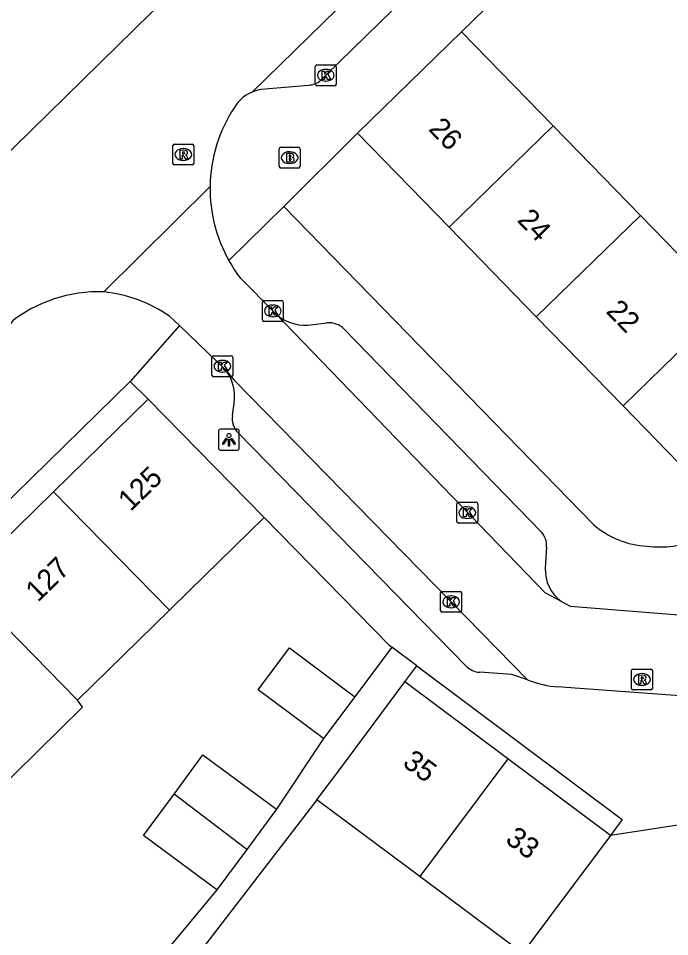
# Model space of a CAD drawing. Extents: x 159222 to 160346, y 381249 to 382166.
# Drawn here: x 159523.05 to 159554.22, y 381384.14 to 381428.08 of the extents above; entities that cross this region are included whole.
import ezdxf

# ---------------------------------------------------------------- set-up
doc = ezdxf.new("R2010")
doc.units = 0
for name, color, linetype in [('IMGEO_Brandkraan', 7, 'Continuous'), ('IMGEO_Kolk', 7, 'Continuous'), ('IMGEO_Lichtpunt', 7, 'Continuous'), ('IMGEO_Muur', 7, 'Continuous'), ('IMGEO_Pand', 7, 'Continuous'), ('IMGEO_Pand_nummerreeks', 7, 'Continuous'), ('IMGEO_Rijbaan_lokaal_gesloten', 7, 'Continuous'), ('IMGEO_Rijbaan_lokaal_open', 7, 'Continuous'), ('IMGEO_Rioolput', 7, 'Continuous'), ('IMGEO_Voetpad_open', 7, 'Continuous')]:
    doc.layers.add(name, color=color, linetype=linetype)

msp = doc.modelspace()

# ---------------------------------------------------------------- linework, layer by layer
at = {"layer": 'IMGEO_Brandkraan'}
for p, q in [((159535.53, 381420.985), (159535.53, 381421.837)), ((159535.605, 381421.911), (159536.457, 381421.911)), ((159536.018, 381421.691), (159536.043, 381421.691)), ((159536.531, 381421.837), (159536.531, 381420.985)), ((159536.041, 381421.131), (159536.016, 381421.131)), ((159536.457, 381420.911), (159535.605, 381420.911))]:
    msp.add_line(p, q, dxfattribs=at)
for points in [[(159535.53, 381420.985), (159535.53, 381421.837)], [(159535.605, 381421.911), (159536.457, 381421.911)], [(159535.878, 381421.611), (159535.878, 381421.211), (159536.091, 381421.211)], [(159536.109, 381421.611), (159535.878, 381421.611)], [(159536.057, 381421.53), (159536.003, 381421.53), (159536.003, 381421.454)], [(159536.531, 381421.837), (159536.531, 381420.985)], [(159536.003, 381421.454), (159536.056, 381421.454)], [(159536.065, 381421.378), (159536.003, 381421.378), (159536.003, 381421.297)], [(159536.003, 381421.297), (159536.065, 381421.297)], [(159536.457, 381420.911), (159535.605, 381420.911)]]:
    msp.add_lwpolyline(points, dxfattribs=at)
for centre, radius, start, end in [((159535.607, 381421.835), 0.0765, 91.552, 178.448), ((159535.607, 381421.835), 0.0765, 91.552, 178.448), ((159536.058, 381421.492), 0.0379, 267.8285, 90.9355), ((159536.113, 381421.466), 0.145, 59.4692, 91.5367), ((159536.138, 381421.513), 0.0922, 285.5137, 58.1501), ((159536.455, 381421.835), 0.0765, 1.552, 88.448), ((159536.455, 381421.835), 0.0765, 1.552, 88.448), ((159536.066, 381421.337), 0.0404, 269.8759, 90.5077), ((159536.097, 381421.462), 0.251, 268.6676, 293.5347), ((159536.143, 381421.321), 0.105, 301.3115, 78.989), ((159535.607, 381420.987), 0.0765, 181.552, 268.448), ((159535.607, 381420.987), 0.0765, 181.552, 268.448), ((159536.455, 381420.987), 0.0765, 271.552, 358.448), ((159536.455, 381420.987), 0.0765, 271.552, 358.448)]:
    msp.add_arc(centre, radius, start, end, dxfattribs=at)
for centre, major_axis, ratio, start_param, end_param in [((159536.017, 381421.411), (-0.387, 0.002), 0.722429, 4.712389, 7.853982), ((159536.042, 381421.411), (-0.39, 0.002), 0.717154, 1.570796, 4.712389)]:
    msp.add_ellipse(centre, major_axis=major_axis, ratio=ratio, start_param=start_param, end_param=end_param, dxfattribs=at)
at = {"layer": 'IMGEO_Kolk'}
for p, q in [((159537.259, 381424.928), (159537.259, 381425.78)), ((159537.334, 381425.854), (159538.186, 381425.854)), ((159537.747, 381425.634), (159537.772, 381425.634)), ((159538.26, 381425.78), (159538.26, 381424.928)), ((159537.77, 381425.074), (159537.745, 381425.074)), ((159538.186, 381424.854), (159537.334, 381424.854)), ((159534.725, 381413.649), (159534.725, 381414.501)), ((159534.8, 381414.575), (159535.652, 381414.575)), ((159535.726, 381414.501), (159535.726, 381413.649)), ((159535.213, 381414.355), (159535.238, 381414.355)), ((159535.236, 381413.795), (159535.211, 381413.795)), ((159535.652, 381413.575), (159534.8, 381413.575)), ((159532.31, 381411.003), (159532.31, 381411.855)), ((159532.385, 381411.929), (159533.237, 381411.929)), ((159533.311, 381411.855), (159533.311, 381411.003)), ((159532.798, 381411.709), (159532.823, 381411.709)), ((159532.821, 381411.149), (159532.796, 381411.149)), ((159533.237, 381410.929), (159532.385, 381410.929)), ((159544.031, 381403.998), (159544.031, 381404.85)), ((159544.106, 381404.924), (159544.958, 381404.924)), ((159545.032, 381404.85), (159545.032, 381403.998)), ((159544.519, 381404.704), (159544.544, 381404.704)), ((159544.542, 381404.144), (159544.517, 381404.144)), ((159544.958, 381403.924), (159544.106, 381403.924)), ((159543.256, 381399.73), (159543.256, 381400.582)), ((159543.331, 381400.656), (159544.183, 381400.656)), ((159543.744, 381400.436), (159543.769, 381400.436)), ((159544.257, 381400.582), (159544.257, 381399.73)), ((159544.183, 381399.656), (159543.331, 381399.656)), ((159543.767, 381399.876), (159543.742, 381399.876))]:
    msp.add_line(p, q, dxfattribs=at)
for points in [[(159537.259, 381424.928), (159537.259, 381425.78)], [(159537.334, 381425.854), (159538.186, 381425.854)], [(159537.58, 381425.554), (159537.703, 381425.554), (159537.703, 381425.403), (159537.833, 381425.554), (159537.997, 381425.554), (159537.851, 381425.403), (159538.004, 381425.154), (159537.852, 381425.154), (159537.767, 381425.318), (159537.703, 381425.251), (159537.703, 381425.154), (159537.58, 381425.154), (159537.58, 381425.554)], [(159538.26, 381425.78), (159538.26, 381424.928)], [(159538.186, 381424.854), (159537.334, 381424.854)], [(159534.725, 381413.649), (159534.725, 381414.501)], [(159534.8, 381414.575), (159535.652, 381414.575)], [(159535.726, 381414.501), (159535.726, 381413.649)], [(159535.046, 381414.275), (159535.169, 381414.275), (159535.169, 381414.124), (159535.299, 381414.275), (159535.463, 381414.275), (159535.317, 381414.124), (159535.47, 381413.875), (159535.318, 381413.875), (159535.233, 381414.039), (159535.169, 381413.972), (159535.169, 381413.875), (159535.046, 381413.875), (159535.046, 381414.275)], [(159535.652, 381413.575), (159534.8, 381413.575)], [(159532.31, 381411.003), (159532.31, 381411.855)], [(159532.385, 381411.929), (159533.237, 381411.929)], [(159533.311, 381411.855), (159533.311, 381411.003)], [(159532.631, 381411.629), (159532.754, 381411.629), (159532.754, 381411.478), (159532.884, 381411.629), (159533.048, 381411.629), (159532.902, 381411.478), (159533.055, 381411.229), (159532.903, 381411.229), (159532.818, 381411.393), (159532.754, 381411.326), (159532.754, 381411.229), (159532.631, 381411.229), (159532.631, 381411.629)], [(159533.237, 381410.929), (159532.385, 381410.929)], [(159544.031, 381403.998), (159544.031, 381404.85)], [(159544.106, 381404.924), (159544.958, 381404.924)], [(159545.032, 381404.85), (159545.032, 381403.998)], [(159544.352, 381404.624), (159544.475, 381404.624), (159544.475, 381404.473), (159544.605, 381404.624), (159544.769, 381404.624), (159544.623, 381404.473), (159544.776, 381404.224), (159544.624, 381404.224), (159544.539, 381404.388), (159544.475, 381404.321), (159544.475, 381404.224), (159544.352, 381404.224), (159544.352, 381404.624)], [(159544.958, 381403.924), (159544.106, 381403.924)], [(159543.256, 381399.73), (159543.256, 381400.582)], [(159543.331, 381400.656), (159544.183, 381400.656)], [(159544.257, 381400.582), (159544.257, 381399.73)], [(159543.577, 381400.356), (159543.7, 381400.356), (159543.7, 381400.205), (159543.83, 381400.356), (159543.994, 381400.356), (159543.848, 381400.205), (159544.001, 381399.956), (159543.849, 381399.956), (159543.764, 381400.12), (159543.7, 381400.053), (159543.7, 381399.956), (159543.577, 381399.956), (159543.577, 381400.356)], [(159544.183, 381399.656), (159543.331, 381399.656)]]:
    msp.add_lwpolyline(points, dxfattribs=at)
for centre, start, end in [((159537.336, 381425.778), 91.552, 178.448), ((159537.336, 381425.778), 91.552, 178.448), ((159538.184, 381425.778), 1.552, 88.448), ((159538.184, 381425.778), 1.552, 88.448), ((159537.336, 381424.93), 181.552, 268.448), ((159537.336, 381424.93), 181.552, 268.448), ((159538.184, 381424.93), 271.552, 358.448), ((159538.184, 381424.93), 271.552, 358.448), ((159534.802, 381414.499), 91.552, 178.448), ((159534.802, 381414.499), 91.552, 178.448), ((159535.65, 381414.499), 1.552, 88.448), ((159535.65, 381414.499), 1.552, 88.448), ((159534.802, 381413.651), 181.552, 268.448), ((159534.802, 381413.651), 181.552, 268.448), ((159535.65, 381413.651), 271.552, 358.448), ((159535.65, 381413.651), 271.552, 358.448), ((159532.387, 381411.853), 91.552, 178.448), ((159532.387, 381411.853), 91.552, 178.448), ((159533.235, 381411.853), 1.552, 88.448), ((159533.235, 381411.853), 1.552, 88.448), ((159532.387, 381411.005), 181.552, 268.448), ((159532.387, 381411.005), 181.552, 268.448), ((159533.235, 381411.005), 271.552, 358.448), ((159533.235, 381411.005), 271.552, 358.448), ((159544.108, 381404.848), 91.552, 178.448), ((159544.108, 381404.848), 91.552, 178.448), ((159544.956, 381404.848), 1.552, 88.448), ((159544.956, 381404.848), 1.552, 88.448), ((159544.108, 381404), 181.552, 268.448), ((159544.108, 381404), 181.552, 268.448), ((159544.956, 381404), 271.552, 358.448), ((159544.956, 381404), 271.552, 358.448), ((159543.333, 381400.58), 91.552, 178.448), ((159543.333, 381400.58), 91.552, 178.448), ((159544.181, 381400.58), 1.552, 88.448), ((159544.181, 381400.58), 1.552, 88.448), ((159543.333, 381399.732), 181.552, 268.448), ((159543.333, 381399.732), 181.552, 268.448), ((159544.181, 381399.732), 271.552, 358.448), ((159544.181, 381399.732), 271.552, 358.448)]:
    msp.add_arc(centre, 0.0765, start, end, dxfattribs=at)
for centre, major_axis, ratio, start_param, end_param in [((159537.746, 381425.354), (-0.387, 0.002), 0.722429, 4.712389, 7.853982), ((159537.771, 381425.354), (-0.39, 0.002), 0.717154, 1.570796, 4.712389), ((159535.212, 381414.075), (-0.387, 0.002), 0.722429, 4.712389, 7.853982), ((159535.237, 381414.075), (-0.39, 0.002), 0.717154, 1.570796, 4.712389), ((159532.797, 381411.429), (-0.387, 0.002), 0.722429, 4.712389, 7.853982), ((159532.822, 381411.429), (-0.39, 0.002), 0.717154, 1.570796, 4.712389), ((159544.518, 381404.424), (-0.387, 0.002), 0.722429, 4.712389, 7.853982), ((159544.543, 381404.424), (-0.39, 0.002), 0.717154, 1.570796, 4.712389), ((159543.743, 381400.156), (-0.387, 0.002), 0.722429, 4.712389, 7.853982), ((159543.768, 381400.156), (-0.39, 0.002), 0.717154, 1.570796, 4.712389)]:
    msp.add_ellipse(centre, major_axis=major_axis, ratio=ratio, start_param=start_param, end_param=end_param, dxfattribs=at)
at = {"layer": 'IMGEO_Lichtpunt'}
for p, q in [((159533.527, 381408.412), (159532.719, 381408.412)), ((159533.527, 381408.412), (159532.719, 381408.412)), ((159532.625, 381408.317), (159532.625, 381407.51)), ((159532.625, 381408.317), (159532.625, 381407.51)), ((159533.621, 381407.51), (159533.621, 381408.317)), ((159533.621, 381407.51), (159533.621, 381408.317)), ((159532.719, 381407.416), (159533.527, 381407.416)), ((159532.719, 381407.416), (159533.527, 381407.416))]:
    msp.add_line(p, q, dxfattribs=at)
for points in [[(159532.999, 381407.981), (159533.038, 381407.953), (159532.85, 381407.691), (159532.812, 381407.718), (159532.999, 381407.981)], [(159533.101, 381407.933), (159533.148, 381407.933), (159533.148, 381407.611), (159533.101, 381407.611), (159533.101, 381407.933)], [(159533.211, 381407.953), (159533.249, 381407.98), (159533.436, 381407.718), (159533.397, 381407.69), (159533.211, 381407.953)]]:
    msp.add_lwpolyline(points, dxfattribs=at)
msp.add_circle((159533.124, 381408.115), 0.0994, dxfattribs=at)
for centre, start, end in [((159532.719, 381408.317), 90, 180), ((159532.719, 381408.317), 90, 180), ((159533.527, 381408.317), 0, 90), ((159533.527, 381408.317), 0, 90), ((159532.719, 381407.51), 180, 270), ((159532.719, 381407.51), 180, 270), ((159533.527, 381407.51), 270, 0), ((159533.527, 381407.51), 270, 360)]:
    msp.add_arc(centre, 0.0946, start, end, dxfattribs=at)
at = {"layer": 'IMGEO_Muur'}
msp.add_lwpolyline([(159540.781, 381398.099), (159534.803, 381404.193)], dxfattribs=at)
at = {"layer": 'IMGEO_Pand'}
for points in [[(159539.277, 381422.576), (159544.261, 381427.431)], [(159544.261, 381427.431), (159548.642, 381422.933)], [(159548.642, 381422.933), (159543.659, 381418.078)], [(159548.642, 381422.933), (159552.816, 381418.649)], [(159543.659, 381418.078), (159539.277, 381422.576)], [(159547.832, 381413.793), (159552.816, 381418.649)], [(159552.816, 381418.649), (159556.971, 381414.383)], [(159547.832, 381413.793), (159543.659, 381418.078)], [(159556.971, 381414.383), (159561.255, 381409.985), (159567.026, 381412.071), (159568.52, 381407.973), (159561.062, 381405.254), (159558.383, 381407.188), (159556.271, 381405.13), (159551.987, 381409.527)], [(159556.971, 381414.383), (159551.987, 381409.527)], [(159551.987, 381409.527), (159547.832, 381413.793)], [(159529.252, 381409.859), (159524.724, 381405.421)], [(159529.252, 381409.859), (159534.803, 381404.193)], [(159524.724, 381405.421), (159520.331, 381401.117)], [(159524.724, 381405.421), (159530.275, 381399.757)], [(159530.275, 381399.757), (159531.232, 381400.694), (159534.803, 381404.193)], [(159525.882, 381395.453), (159520.331, 381401.117)], [(159525.882, 381395.453), (159530.275, 381399.757)], [(159537.652, 381393.612), (159534.527, 381395.944), (159536.022, 381397.948), (159539.147, 381395.616)], [(159537.336, 381390.68), (159538.555, 381392.313), (159541.545, 381396.32)], [(159546.464, 381392.649), (159541.545, 381396.32)], [(159539.147, 381395.616), (159537.652, 381393.612)], [(159521.776, 381390.857), (159526.123, 381395.12), (159525.882, 381395.453)], [(159530.5, 381390.959), (159531.881, 381392.828), (159535.399, 381390.23)], [(159546.464, 381392.649), (159542.257, 381387.008)], [(159551.383, 381388.978), (159546.464, 381392.649)], [(159532.55, 381386.372), (159529.032, 381388.97), (159530.5, 381390.959)], [(159533.978, 381388.307), (159530.5, 381390.959)], [(159542.257, 381387.008), (159537.336, 381390.68)], [(159535.399, 381390.23), (159533.978, 381388.307)], [(159551.383, 381388.978), (159548.394, 381384.971), (159547.175, 381383.338), (159542.257, 381387.008)], [(159533.978, 381388.307), (159532.55, 381386.372)]]:
    msp.add_lwpolyline(points, dxfattribs=at)
at = {"layer": 'IMGEO_Rijbaan_lokaal_gesloten'}
for points in [[(159534.231, 381424.544), (159557.976, 381447.733)], [(159533.511, 381432.388), (159520.372, 381419.512)], [(159534.231, 381424.544), (159534.207, 381424.535), (159534.062, 381424.464), (159533.924, 381424.381), (159533.795, 381424.285), (159533.674, 381424.179), (159533.563, 381424.062), (159533.464, 381423.935), (159533.384, 381423.815)], [(159532.224, 381420.031), (159527.135, 381414.989)], [(159527.135, 381414.989), (159526.531, 381414.985), (159525.93, 381414.928), (159525.336, 381414.817), (159524.755, 381414.653), (159524.19, 381414.439), (159523.647, 381414.174), (159523.13, 381413.862), (159522.909, 381413.709), (159522.787, 381413.6), (159522.676, 381413.48), (159522.6, 381413.383)]]:
    msp.add_lwpolyline(points, dxfattribs=at)
msp.add_arc((159539.296, 381419.933), 7.073, 146.7098, 179.204, dxfattribs=at)
at = {"layer": 'IMGEO_Rijbaan_lokaal_open'}
for points in [[(159533.656, 381415.663), (159535.334, 381413.963)], [(159530.28, 381413.823), (159530.752, 381413.378)], [(159549.041, 381400.165), (159548.266, 381400.58), (159535.334, 381413.963)], [(159532.945, 381411.28), (159530.752, 381413.378)], [(159532.945, 381411.28), (159533.378, 381410.764), (159547.413, 381396.42)], [(159549.041, 381400.165), (159549.457, 381399.942), (159555.859, 381399.431), (159556.544, 381399.493)], [(159557.302, 381395.935), (159556.228, 381395.543), (159549.264, 381396.063), (159548.892, 381396.081)]]:
    msp.add_lwpolyline(points, dxfattribs=at)
for centre, radius, start, end in [((159539.288, 381419.928), 7.065, 179.1685, 209.1323), ((159539.348, 381419.966), 7.136, 209.1632, 217.0891), ((159526.488, 381408.419), 6.601, 54.9406, 84.3751), ((159549.338, 381401.422), 5.36, 248.9529, 265.2276)]:
    msp.add_arc(centre, radius, start, end, dxfattribs=at)
at = {"layer": 'IMGEO_Rioolput'}
for p, q in [((159530.441, 381421.136), (159530.441, 381421.988)), ((159530.516, 381422.062), (159531.368, 381422.062)), ((159531.442, 381421.988), (159531.442, 381421.136)), ((159530.929, 381421.842), (159530.954, 381421.842)), ((159530.952, 381421.282), (159530.927, 381421.282)), ((159531.368, 381421.062), (159530.516, 381421.062)), ((159552.466, 381396.939), (159553.318, 381396.939)), ((159552.391, 381396.013), (159552.391, 381396.865)), ((159552.879, 381396.719), (159552.904, 381396.719)), ((159553.392, 381396.865), (159553.392, 381396.013)), ((159552.902, 381396.159), (159552.877, 381396.159)), ((159553.318, 381395.939), (159552.466, 381395.939))]:
    msp.add_line(p, q, dxfattribs=at)
for points in [[(159530.441, 381421.136), (159530.441, 381421.988)], [(159530.516, 381422.062), (159531.368, 381422.062)], [(159531.442, 381421.988), (159531.442, 381421.136)], [(159531.03, 381421.76), (159530.778, 381421.762), (159530.778, 381421.362)], [(159530.778, 381421.362), (159530.902, 381421.362), (159530.902, 381421.524), (159530.913, 381421.524)], [(159530.956, 381421.681), (159530.902, 381421.681), (159530.902, 381421.6)], [(159530.902, 381421.6), (159530.954, 381421.6)], [(159530.96, 381421.495), (159531.031, 381421.362), (159531.171, 381421.362), (159531.106, 381421.488)], [(159531.368, 381421.062), (159530.516, 381421.062)], [(159552.466, 381396.939), (159553.318, 381396.939)], [(159552.391, 381396.013), (159552.391, 381396.865)], [(159552.98, 381396.637), (159552.728, 381396.639), (159552.728, 381396.239)], [(159552.906, 381396.558), (159552.852, 381396.558), (159552.852, 381396.477)], [(159552.852, 381396.477), (159552.904, 381396.477)], [(159553.392, 381396.865), (159553.392, 381396.013)], [(159552.728, 381396.239), (159552.852, 381396.239), (159552.852, 381396.401), (159552.863, 381396.401)], [(159552.91, 381396.372), (159552.981, 381396.239), (159553.121, 381396.239), (159553.056, 381396.365)], [(159553.318, 381395.939), (159552.466, 381395.939)]]:
    msp.add_lwpolyline(points, dxfattribs=at)
for centre, radius, start, end in [((159530.518, 381421.986), 0.0765, 91.552, 178.448), ((159530.518, 381421.986), 0.0765, 91.552, 178.448), ((159531.366, 381421.986), 0.0765, 1.552, 88.448), ((159531.366, 381421.986), 0.0765, 1.552, 88.448), ((159530.912, 381421.471), 0.0533, 26.0293, 88.6989), ((159530.938, 381421.789), 0.19, 274.7715, 282.9687), ((159530.962, 381421.585), 0.0964, 77.0061, 93.1865), ((159530.976, 381421.642), 0.0378, 276.6634, 79.6772), ((159531.029, 381421.65), 0.109, 350.3612, 89.416), ((159531.027, 381421.65), 0.112, 277.5842, 350.9817), ((159531.011, 381421.435), 0.108, 29.5134, 73.7905), ((159530.518, 381421.138), 0.0765, 181.552, 268.448), ((159530.518, 381421.138), 0.0765, 181.552, 268.448), ((159531.366, 381421.138), 0.0765, 271.552, 358.448), ((159531.366, 381421.138), 0.0765, 271.552, 358.448), ((159552.468, 381396.863), 0.0765, 91.552, 178.448), ((159552.468, 381396.863), 0.0765, 91.552, 178.448), ((159553.316, 381396.863), 0.0765, 1.552, 88.448), ((159553.316, 381396.863), 0.0765, 1.552, 88.448), ((159552.888, 381396.666), 0.19, 274.7715, 282.9687), ((159552.912, 381396.462), 0.0964, 77.0061, 93.1865), ((159552.926, 381396.519), 0.0378, 276.6634, 79.6772), ((159552.979, 381396.527), 0.109, 350.3612, 89.416), ((159552.977, 381396.527), 0.112, 277.5842, 350.9817), ((159552.862, 381396.348), 0.0533, 26.0293, 88.6989), ((159552.961, 381396.312), 0.108, 29.5134, 73.7905), ((159552.468, 381396.015), 0.0765, 181.552, 268.448), ((159552.468, 381396.015), 0.0765, 181.552, 268.448), ((159553.316, 381396.015), 0.0765, 271.552, 358.448), ((159553.316, 381396.015), 0.0765, 271.552, 358.448)]:
    msp.add_arc(centre, radius, start, end, dxfattribs=at)
for centre, major_axis, ratio, start_param, end_param in [((159530.928, 381421.562), (-0.387, 0.002), 0.722429, 4.712389, 7.853982), ((159530.953, 381421.562), (-0.39, 0.002), 0.717154, 1.570796, 4.712389), ((159552.878, 381396.439), (-0.387, 0.002), 0.722429, 4.712389, 7.853982), ((159552.903, 381396.439), (-0.39, 0.002), 0.717154, 1.570796, 4.712389)]:
    msp.add_ellipse(centre, major_axis=major_axis, ratio=ratio, start_param=start_param, end_param=end_param, dxfattribs=at)
at = {"layer": 'IMGEO_Voetpad_open'}
for points in [[(159559.294, 381446.379), (159552.45, 381439.703), (159537.76, 381425.355), (159537.603, 381425.195), (159537.586, 381425.175), (159537.529, 381425.116), (159537.466, 381425.062), (159537.4, 381425.014), (159537.329, 381424.973), (159537.255, 381424.937), (159537.177, 381424.909), (159537.098, 381424.887), (159537.017, 381424.873), (159536.935, 381424.866), (159534.67, 381424.666), (159534.512, 381424.636), (159534.357, 381424.592), (159534.231, 381424.544)], [(159554.351, 381437.259), (159544.261, 381427.431)], [(159539.277, 381422.576), (159535.754, 381419.075)], [(159535.754, 381419.075), (159533.117, 381416.489)], [(159535.754, 381419.075), (159550.571, 381403.862)], [(159530.752, 381413.378), (159528.398, 381410.697)], [(159536.903, 381413.394), (159537.812, 381413.5)], [(159538.645, 381413.204), (159548.048, 381403.529)], [(159492.843, 381375.889), (159500, 381382.896), (159528.398, 381410.697)], [(159528.398, 381410.697), (159529.252, 381409.859)], [(159533.29, 381409.078), (159533.372, 381409.657)], [(159544.482, 381397.081), (159533.565, 381408.238)], [(159534.803, 381404.193), (159540.781, 381398.099), (159540.921, 381397.994)], [(159548.329, 381402.766), (159548.263, 381401.769)], [(159540.921, 381397.994), (159539.147, 381395.616)], [(159542.123, 381397.095), (159540.921, 381397.994)], [(159541.545, 381396.32), (159542.123, 381397.095)], [(159542.123, 381397.095), (159551.943, 381389.746), (159551.383, 381388.978)], [(159547.413, 381396.42), (159546.659, 381396.679), (159545.128, 381396.783)], [(159537.652, 381393.612), (159535.399, 381390.23)], [(159537.336, 381390.68), (159530.142, 381381.33), (159533.575, 381378.895)], [(159558.696, 381390.481), (159557.215, 381389.866), (159551.383, 381388.978)], [(159532.55, 381386.372), (159529.359, 381382.532), (159527.138, 381380.167)]]:
    msp.add_lwpolyline(points, dxfattribs=at)
for centre, radius, start, end in [((159536.771, 381415.478), 2.088, 226.5122, 273.6213), ((159537.928, 381412.506), 1, 44.2149, 96.6606), ((159531.312, 381409.983), 2.086, 351.0209, 38.4593), ((159534.283, 381408.938), 1.003, 171.9827, 224.2722), ((159547.334, 381402.833), 0.997, 356.1481, 44.2877), ((159553.359, 381407.031), 4.221, 228.6546, 266.9275), ((159553.731, 381407.976), 5.195, 263.3872, 291.1084), ((159550.12, 381401.679), 1.859, 177.2211, 234.5292), ((159545.2, 381397.788), 1.007, 224.5611, 265.9112)]:
    msp.add_arc(centre, radius, start, end, dxfattribs=at)

# ---------------------------------------------------------------- texts
at = {"layer": 'IMGEO_Pand_nummerreeks'}
for s, rotation, p in [('26', 314.2481, (159542.631, 381422.745)), ('24', 314.2481, (159546.879, 381418.383)), ('22', 314.2481, (159551.125, 381414.025)), ('125', 44.419, (159528.416, 381404.447)), ('127', 44.419, (159523.989, 381400.11)), ('35', 323.2664, (159541.381, 381392.349)), ('33', 323.2664, (159546.3, 381388.678))]:
    msp.add_text(s, height=1, rotation=rotation, dxfattribs=at).set_placement(p)

doc.saveas('drawing.dxf')
